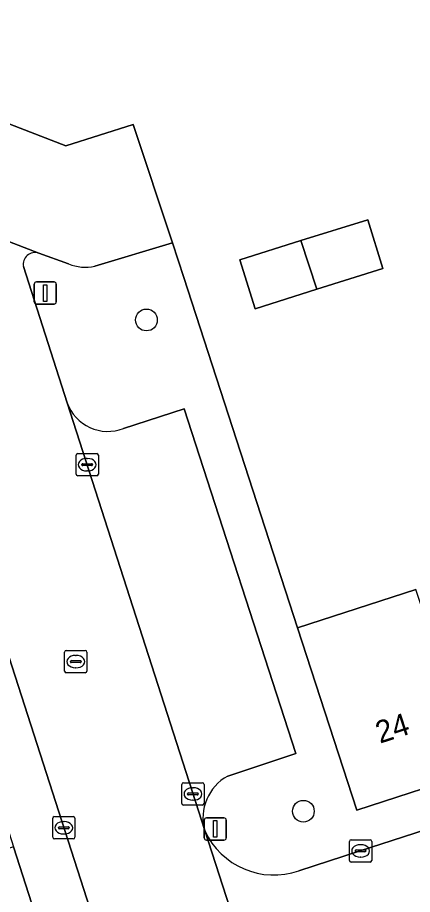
# Model space of a CAD drawing. Extents: x 159371 to 159986, y 382987 to 383597.
# Drawn here: x 159467.7 to 159485.47, y 383349.44 to 383388.85 of the extents above; entities that cross this region are included whole.
import ezdxf

# ---------------------------------------------------------------- set-up
doc = ezdxf.new("R2010")
doc.units = 0
for name, color, linetype in [('IMGEO_Boom', 7, 'Continuous'), ('IMGEO_Erf', 7, 'Continuous'), ('IMGEO_Kolk', 7, 'Continuous'), ('IMGEO_Lichtmast', 7, 'Continuous'), ('IMGEO_Muur', 7, 'Continuous'), ('IMGEO_Pand', 7, 'Continuous'), ('IMGEO_Pand_nummerreeks', 7, 'Continuous'), ('IMGEO_Parkeervlak_open', 7, 'Continuous'), ('IMGEO_Rijbaan_lokaal_open', 7, 'Continuous'), ('IMGEO_Rioolput', 7, 'Continuous'), ('IMGEO_Voetpad_open', 7, 'Continuous')]:
    doc.layers.add(name, color=color, linetype=linetype)

msp = doc.modelspace()

# ---------------------------------------------------------------- linework, layer by layer
at = {"layer": 'IMGEO_Boom'}
for centre in [(159473.504, 383375.257), (159480.563, 383353.183)]:
    msp.add_circle(centre, 0.489, dxfattribs=at)
at = {"layer": 'IMGEO_Erf'}
msp.add_lwpolyline([(159457.371, 383396.581), (159460.368, 383386.758), (159469.884, 383383.076), (159472.912, 383384.045), (159474.669, 383378.719), (159475.18, 383377.169), (159480.301, 383361.417), (159485.631, 383363.139)], dxfattribs=at)
msp.add_lwpolyline([(159484.144, 383377.568), (159481.177, 383376.638), (159478.389, 383375.764), (159477.701, 383377.959), (159480.456, 383378.822), (159483.457, 383379.763)], close=True, dxfattribs=at)
at = {"layer": 'IMGEO_Kolk'}
for p, q in [((159470.339, 383368.329), (159470.339, 383369.181)), ((159470.414, 383369.255), (159471.266, 383369.255)), ((159470.827, 383369.035), (159470.852, 383369.035)), ((159471.34, 383369.181), (159471.34, 383368.329)), ((159470.598, 383368.749), (159470.598, 383368.761)), ((159471.036, 383368.712), (159470.638, 383368.712)), ((159470.641, 383368.798), (159471.039, 383368.798)), ((159471.082, 383368.761), (159471.082, 383368.749)), ((159471.266, 383368.255), (159470.414, 383368.255)), ((159470.85, 383368.475), (159470.825, 383368.475)), ((159475.095, 383353.533), (159475.095, 383354.385)), ((159475.17, 383354.459), (159476.022, 383354.459)), ((159476.096, 383354.385), (159476.096, 383353.533)), ((159475.354, 383353.953), (159475.354, 383353.965)), ((159475.397, 383354.002), (159475.795, 383354.002)), ((159475.583, 383354.239), (159475.608, 383354.239)), ((159475.838, 383353.965), (159475.838, 383353.953)), ((159475.792, 383353.916), (159475.394, 383353.916)), ((159475.606, 383353.679), (159475.581, 383353.679)), ((159476.022, 383353.459), (159475.17, 383353.459)), ((159469.285, 383352.013), (159469.285, 383352.865)), ((159469.36, 383352.939), (159470.212, 383352.939)), ((159470.286, 383352.865), (159470.286, 383352.013)), ((159469.544, 383352.433), (159469.544, 383352.445)), ((159469.982, 383352.396), (159469.584, 383352.396)), ((159469.587, 383352.482), (159469.985, 383352.482)), ((159469.773, 383352.719), (159469.798, 383352.719)), ((159470.028, 383352.445), (159470.028, 383352.433)), ((159469.796, 383352.159), (159469.771, 383352.159)), ((159470.212, 383351.939), (159469.36, 383351.939)), ((159482.638, 383350.974), (159482.638, 383351.826)), ((159482.713, 383351.9), (159483.565, 383351.9)), ((159483.126, 383351.68), (159483.151, 383351.68)), ((159483.639, 383351.826), (159483.639, 383350.974)), ((159482.897, 383351.394), (159482.897, 383351.406)), ((159483.335, 383351.357), (159482.937, 383351.357)), ((159482.94, 383351.443), (159483.338, 383351.443)), ((159483.381, 383351.406), (159483.381, 383351.394)), ((159483.565, 383350.9), (159482.713, 383350.9)), ((159483.149, 383351.12), (159483.124, 383351.12))]:
    msp.add_line(p, q, dxfattribs=at)
for points in [[(159470.339, 383368.329), (159470.339, 383369.181)], [(159470.414, 383369.255), (159471.266, 383369.255)], [(159471.34, 383369.181), (159471.34, 383368.329)], [(159471.266, 383368.255), (159470.414, 383368.255)], [(159475.095, 383353.533), (159475.095, 383354.385)], [(159475.17, 383354.459), (159476.022, 383354.459)], [(159476.096, 383354.385), (159476.096, 383353.533)], [(159476.022, 383353.459), (159475.17, 383353.459)], [(159469.285, 383352.013), (159469.285, 383352.865)], [(159469.36, 383352.939), (159470.212, 383352.939)], [(159470.286, 383352.865), (159470.286, 383352.013)], [(159470.212, 383351.939), (159469.36, 383351.939)], [(159482.638, 383350.974), (159482.638, 383351.826)], [(159482.713, 383351.9), (159483.565, 383351.9)], [(159483.639, 383351.826), (159483.639, 383350.974)], [(159483.565, 383350.9), (159482.713, 383350.9)]]:
    msp.add_lwpolyline(points, dxfattribs=at)
for centre, radius, start, end in [((159470.416, 383369.179), 0.0765, 91.552, 178.448), ((159470.416, 383369.179), 0.0765, 91.552, 178.448), ((159471.264, 383369.179), 0.0765, 1.552, 88.448), ((159471.264, 383369.179), 0.0765, 1.552, 88.448), ((159470.638, 383368.758), 0.0403, 85.8775, 175.7526), ((159470.635, 383368.748), 0.0366, 178.938, 274.7102), ((159471.039, 383368.755), 0.043, 264.8664, 352.4533), ((159471.043, 383368.76), 0.0386, 1.7309, 96.639), ((159470.416, 383368.331), 0.0765, 181.552, 268.448), ((159470.416, 383368.331), 0.0765, 181.552, 268.448), ((159471.264, 383368.331), 0.0765, 271.552, 358.448), ((159471.264, 383368.331), 0.0765, 271.552, 358.448), ((159475.172, 383354.383), 0.0765, 91.552, 178.448), ((159475.172, 383354.383), 0.0765, 91.552, 178.448), ((159476.02, 383354.383), 0.0765, 1.552, 88.448), ((159476.02, 383354.383), 0.0765, 1.552, 88.448), ((159475.394, 383353.962), 0.0403, 85.8775, 175.7526), ((159475.391, 383353.952), 0.0366, 178.938, 274.7102), ((159475.795, 383353.959), 0.043, 264.8664, 352.4533), ((159475.799, 383353.964), 0.0386, 1.7309, 96.639), ((159475.172, 383353.535), 0.0765, 181.552, 268.448), ((159475.172, 383353.535), 0.0765, 181.552, 268.448), ((159476.02, 383353.535), 0.0765, 271.552, 358.448), ((159476.02, 383353.535), 0.0765, 271.552, 358.448), ((159469.362, 383352.863), 0.0765, 91.552, 178.448), ((159469.362, 383352.863), 0.0765, 91.552, 178.448), ((159470.21, 383352.863), 0.0765, 1.552, 88.448), ((159470.21, 383352.863), 0.0765, 1.552, 88.448), ((159469.584, 383352.442), 0.0403, 85.8775, 175.7526), ((159469.581, 383352.432), 0.0366, 178.938, 274.7102), ((159469.985, 383352.439), 0.043, 264.8664, 352.4533), ((159469.989, 383352.444), 0.0386, 1.7309, 96.639), ((159469.362, 383352.015), 0.0765, 181.552, 268.448), ((159469.362, 383352.015), 0.0765, 181.552, 268.448), ((159470.21, 383352.015), 0.0765, 271.552, 358.448), ((159470.21, 383352.015), 0.0765, 271.552, 358.448), ((159482.715, 383351.824), 0.0765, 91.552, 178.448), ((159482.715, 383351.824), 0.0765, 91.552, 178.448), ((159483.563, 383351.824), 0.0765, 1.552, 88.448), ((159483.563, 383351.824), 0.0765, 1.552, 88.448), ((159482.937, 383351.403), 0.0403, 85.8775, 175.7526), ((159482.934, 383351.393), 0.0366, 178.938, 274.7102), ((159483.338, 383351.4), 0.043, 264.8664, 352.4533), ((159483.342, 383351.405), 0.0386, 1.7309, 96.639), ((159482.715, 383350.976), 0.0765, 181.552, 268.448), ((159482.715, 383350.976), 0.0765, 181.552, 268.448), ((159483.563, 383350.976), 0.0765, 271.552, 358.448), ((159483.563, 383350.976), 0.0765, 271.552, 358.448)]:
    msp.add_arc(centre, radius, start, end, dxfattribs=at)
for centre, major_axis, ratio, start_param, end_param in [((159470.826, 383368.755), (-0.387, 0.002), 0.722429, 4.712389, 7.853982), ((159470.851, 383368.755), (-0.39, 0.002), 0.717154, 1.570796, 4.712389), ((159475.582, 383353.959), (-0.387, 0.002), 0.722429, 4.712389, 7.853982), ((159475.607, 383353.959), (-0.39, 0.002), 0.717154, 1.570796, 4.712389), ((159469.772, 383352.439), (-0.387, 0.002), 0.722429, 4.712389, 7.853982), ((159469.797, 383352.439), (-0.39, 0.002), 0.717154, 1.570796, 4.712389), ((159483.125, 383351.4), (-0.387, 0.002), 0.722429, 4.712389, 7.853982), ((159483.15, 383351.4), (-0.39, 0.002), 0.717154, 1.570796, 4.712389)]:
    msp.add_ellipse(centre, major_axis=major_axis, ratio=ratio, start_param=start_param, end_param=end_param, dxfattribs=at)
at = {"layer": 'IMGEO_Lichtmast'}
for p, q in [((159468.458, 383376.069), (159468.458, 383376.869)), ((159468.458, 383376.869), (159468.458, 383376.069)), ((159468.558, 383376.969), (159469.348, 383376.969)), ((159469.348, 383376.969), (159468.558, 383376.969)), ((159469.448, 383376.869), (159469.448, 383376.069)), ((159469.448, 383376.069), (159469.448, 383376.869)), ((159469.348, 383375.969), (159468.558, 383375.969)), ((159468.558, 383375.969), (159469.348, 383375.969)), ((159476.103, 383351.986), (159476.103, 383352.786)), ((159476.103, 383352.786), (159476.103, 383351.986)), ((159476.203, 383352.886), (159476.993, 383352.886)), ((159476.993, 383352.886), (159476.203, 383352.886)), ((159477.093, 383352.786), (159477.093, 383351.986)), ((159477.093, 383351.986), (159477.093, 383352.786)), ((159476.993, 383351.886), (159476.203, 383351.886)), ((159476.203, 383351.886), (159476.993, 383351.886))]:
    msp.add_line(p, q, dxfattribs=at)
for points in [[(159468.878, 383376.844), (159469.028, 383376.844), (159469.028, 383376.094), (159468.878, 383376.094), (159468.878, 383376.844)], [(159476.523, 383352.761), (159476.673, 383352.761), (159476.673, 383352.011), (159476.523, 383352.011), (159476.523, 383352.761)]]:
    msp.add_lwpolyline(points, dxfattribs=at)
for centre, start, end in [((159468.558, 383376.869), 90, 180), ((159468.558, 383376.869), 90, 180), ((159469.348, 383376.869), 0, 90), ((159469.348, 383376.869), 360, 90), ((159468.558, 383376.069), 180, 270), ((159468.558, 383376.069), 180, 270), ((159469.348, 383376.069), 270, 0), ((159469.348, 383376.069), 270, 0), ((159476.203, 383352.786), 90, 180), ((159476.203, 383352.786), 90, 180), ((159476.993, 383352.786), 0, 90), ((159476.993, 383352.786), 360, 90), ((159476.203, 383351.986), 180, 270), ((159476.203, 383351.986), 180, 270), ((159476.993, 383351.986), 270, 0), ((159476.993, 383351.986), 270, 0)]:
    msp.add_arc(centre, 0.1, start, end, dxfattribs=at)
at = {"layer": 'IMGEO_Muur'}
for points in [[(159460.368, 383386.758), (159469.884, 383383.076), (159472.912, 383384.045)], [(159475.18, 383377.169), (159480.301, 383361.417)]]:
    msp.add_lwpolyline(points, dxfattribs=at)
at = {"layer": 'IMGEO_Pand'}
for points in [[(159480.456, 383378.822), (159481.177, 383376.638), (159484.144, 383377.568), (159483.457, 383379.763)], [(159480.456, 383378.822), (159477.701, 383377.959), (159478.389, 383375.764), (159481.177, 383376.638)], [(159485.631, 383363.139), (159480.301, 383361.417), (159482.966, 383353.228), (159488.328, 383354.966)], [(159467.521, 383351.582), (159459.337, 383348.946), (159456.939, 383348.174), (159458.589, 383343.05), (159460.988, 383343.823), (159469.167, 383346.458)]]:
    msp.add_lwpolyline(points, close=True, dxfattribs=at)
at = {"layer": 'IMGEO_Parkeervlak_open'}
for points in [[(159469.944, 383371.54), (159476.124, 383352.314)], [(159477.161, 383354.762), (159480.222, 383355.774), (159475.195, 383371.27), (159472.466, 383370.386)]]:
    msp.add_lwpolyline(points, dxfattribs=at)
for centre, radius, start, end in [((159471.756, 383372.168), 1.918, 199.1143, 291.7106), ((159478.185, 383352.885), 2.139, 118.6105, 195.4734)]:
    msp.add_arc(centre, radius, start, end, dxfattribs=at)
at = {"layer": 'IMGEO_Rijbaan_lokaal_open'}
for points in [[(159471.189, 383377.673), (159474.669, 383378.719), (159472.912, 383384.045), (159469.884, 383383.076), (159460.368, 383386.758), (159454.473, 383389.037), (159452.629, 383395.11), (159450.363, 383402.446)], [(159441.119, 383389.04), (159439.99, 383386.225), (159438.86, 383383.41), (159438.645, 383375.704), (159439.372, 383375.937), (159442.119, 383376.82), (159444.867, 383377.703), (159447.614, 383378.586), (159450.362, 383379.469), (159453.109, 383380.351), (159455.857, 383381.234), (159458.604, 383382.117), (159462.163, 383380.754), (159468.664, 383378.261), (159470, 383377.778)], [(159468.664, 383378.261), (159462.163, 383380.754)], [(159476.124, 383352.314), (159469.944, 383371.54), (159467.972, 383377.657)], [(159463.343, 383377.332), (159460.483, 383376.381), (159457.704, 383375.486), (159454.957, 383374.601), (159452.21, 383373.716), (159449.463, 383372.831), (159446.716, 383371.946), (159443.97, 383371.061), (159441.223, 383370.176), (159439.861, 383369.737), (159441.143, 383360.903), (159442.421, 383361.307), (159445.262, 383362.222), (159448.104, 383363.138), (159450.945, 383364.053), (159453.786, 383364.968), (159456.627, 383365.883), (159459.469, 383366.799), (159462.31, 383367.714), (159462.363, 383367.551), (159464.643, 383368.374), (159482.73, 383312.288)], [(159517.827, 383356.31), (159517.861, 383356.203), (159520.015, 383349.441), (159520.44, 383348.178), (159526.135, 383350.002), (159524.915, 383353.767), (159523.137, 383359.253), (159521.358, 383364.743), (159521.301, 383364.919), (159515.428, 383363.746), (159516.008, 383362.039), (159500, 383356.858), (159483.081, 383351.382), (159480.363, 383350.502)], [(159479.838, 383340.87), (159476.124, 383352.314)], [(159476.124, 383352.314), (159479.838, 383340.87), (159479.77, 383341.31)]]:
    msp.add_lwpolyline(points, dxfattribs=at)
for centre, radius, start, end in [((159468.494, 383377.757), 0.532, 71.3908, 190.8402), ((159470.769, 383379.702), 2.072, 248.2114, 281.6952), ((159479.246, 383353.753), 3.438, 204.7474, 288.9631)]:
    msp.add_arc(centre, radius, start, end, dxfattribs=at)
at = {"layer": 'IMGEO_Rioolput'}
for p, q in [((159469.823, 383359.48), (159469.823, 383360.332)), ((159469.898, 383360.406), (159470.75, 383360.406)), ((159470.824, 383360.332), (159470.824, 383359.48)), ((159470.082, 383359.9), (159470.082, 383359.912)), ((159470.52, 383359.863), (159470.122, 383359.863)), ((159470.125, 383359.949), (159470.523, 383359.949)), ((159470.311, 383360.186), (159470.336, 383360.186)), ((159470.566, 383359.912), (159470.566, 383359.9)), ((159470.334, 383359.626), (159470.309, 383359.626)), ((159470.75, 383359.406), (159469.898, 383359.406))]:
    msp.add_line(p, q, dxfattribs=at)
for points in [[(159469.823, 383359.48), (159469.823, 383360.332)], [(159469.898, 383360.406), (159470.75, 383360.406)], [(159470.824, 383360.332), (159470.824, 383359.48)], [(159470.75, 383359.406), (159469.898, 383359.406)]]:
    msp.add_lwpolyline(points, dxfattribs=at)
for centre, radius, start, end in [((159469.9, 383360.33), 0.0765, 91.552, 178.448), ((159469.9, 383360.33), 0.0765, 91.552, 178.448), ((159470.748, 383360.33), 0.0765, 1.552, 88.448), ((159470.748, 383360.33), 0.0765, 1.552, 88.448), ((159470.122, 383359.909), 0.0403, 85.8775, 175.7526), ((159470.119, 383359.899), 0.0366, 178.938, 274.7102), ((159470.523, 383359.906), 0.043, 264.8664, 352.4533), ((159470.527, 383359.911), 0.0386, 1.7309, 96.639), ((159469.9, 383359.482), 0.0765, 181.552, 268.448), ((159469.9, 383359.482), 0.0765, 181.552, 268.448), ((159470.748, 383359.482), 0.0765, 271.552, 358.448), ((159470.748, 383359.482), 0.0765, 271.552, 358.448)]:
    msp.add_arc(centre, radius, start, end, dxfattribs=at)
for centre, major_axis, ratio, start_param, end_param in [((159470.31, 383359.906), (-0.387, 0.002), 0.722429, 4.712389, 7.853982), ((159470.335, 383359.906), (-0.39, 0.002), 0.717154, 1.570796, 4.712389)]:
    msp.add_ellipse(centre, major_axis=major_axis, ratio=ratio, start_param=start_param, end_param=end_param, dxfattribs=at)
at = {"layer": 'IMGEO_Voetpad_open'}
for points in [[(159480.363, 383350.502), (159483.081, 383351.382), (159500, 383356.858), (159516.008, 383362.039), (159515.428, 383363.746), (159514.217, 383363.357), (159508.89, 383361.63), (159503.719, 383359.954), (159500, 383358.749), (159498.604, 383358.297), (159493.451, 383356.626), (159488.328, 383354.966), (159482.966, 383353.228), (159480.301, 383361.417), (159475.18, 383377.169), (159474.669, 383378.719), (159471.189, 383377.673)], [(159470, 383377.778), (159468.664, 383378.261)], [(159467.972, 383377.657), (159469.944, 383371.54)], [(159472.466, 383370.386), (159475.195, 383371.27), (159480.222, 383355.774), (159477.161, 383354.762)], [(159497.907, 383277.902), (159491.962, 383283.659), (159483.583, 383309.643), (159482.73, 383312.288), (159464.643, 383368.374), (159462.363, 383367.551), (159464.145, 383362.091), (159465.857, 383356.763), (159467.521, 383351.582), (159469.167, 383346.458), (159470.822, 383341.306), (159472.472, 383336.172), (159474.127, 383331.019), (159475.849, 383325.659), (159476.326, 383324.233), (159478.057, 383318.86), (159479.71, 383313.73), (159481.375, 383308.56), (159483.031, 383303.42), (159484.708, 383298.213), (159486.361, 383293.083), (159488.026, 383287.914), (159489.673, 383282.802), (159491.407, 383277.42)]]:
    msp.add_lwpolyline(points, dxfattribs=at)
for centre, radius, start, end in [((159468.494, 383377.757), 0.532, 71.3908, 190.8402), ((159470.769, 383379.702), 2.072, 248.2114, 281.6952), ((159471.756, 383372.168), 1.918, 199.1143, 291.7106), ((159478.185, 383352.885), 2.139, 118.6105, 195.4734), ((159479.246, 383353.753), 3.438, 204.7474, 288.9631)]:
    msp.add_arc(centre, radius, start, end, dxfattribs=at)

# ---------------------------------------------------------------- texts
at = {"layer": 'IMGEO_Pand_nummerreeks'}
msp.add_text('24', height=1, rotation=17.9584, dxfattribs=at).set_placement((159484.007, 383356.214))

doc.saveas('drawing.dxf')
